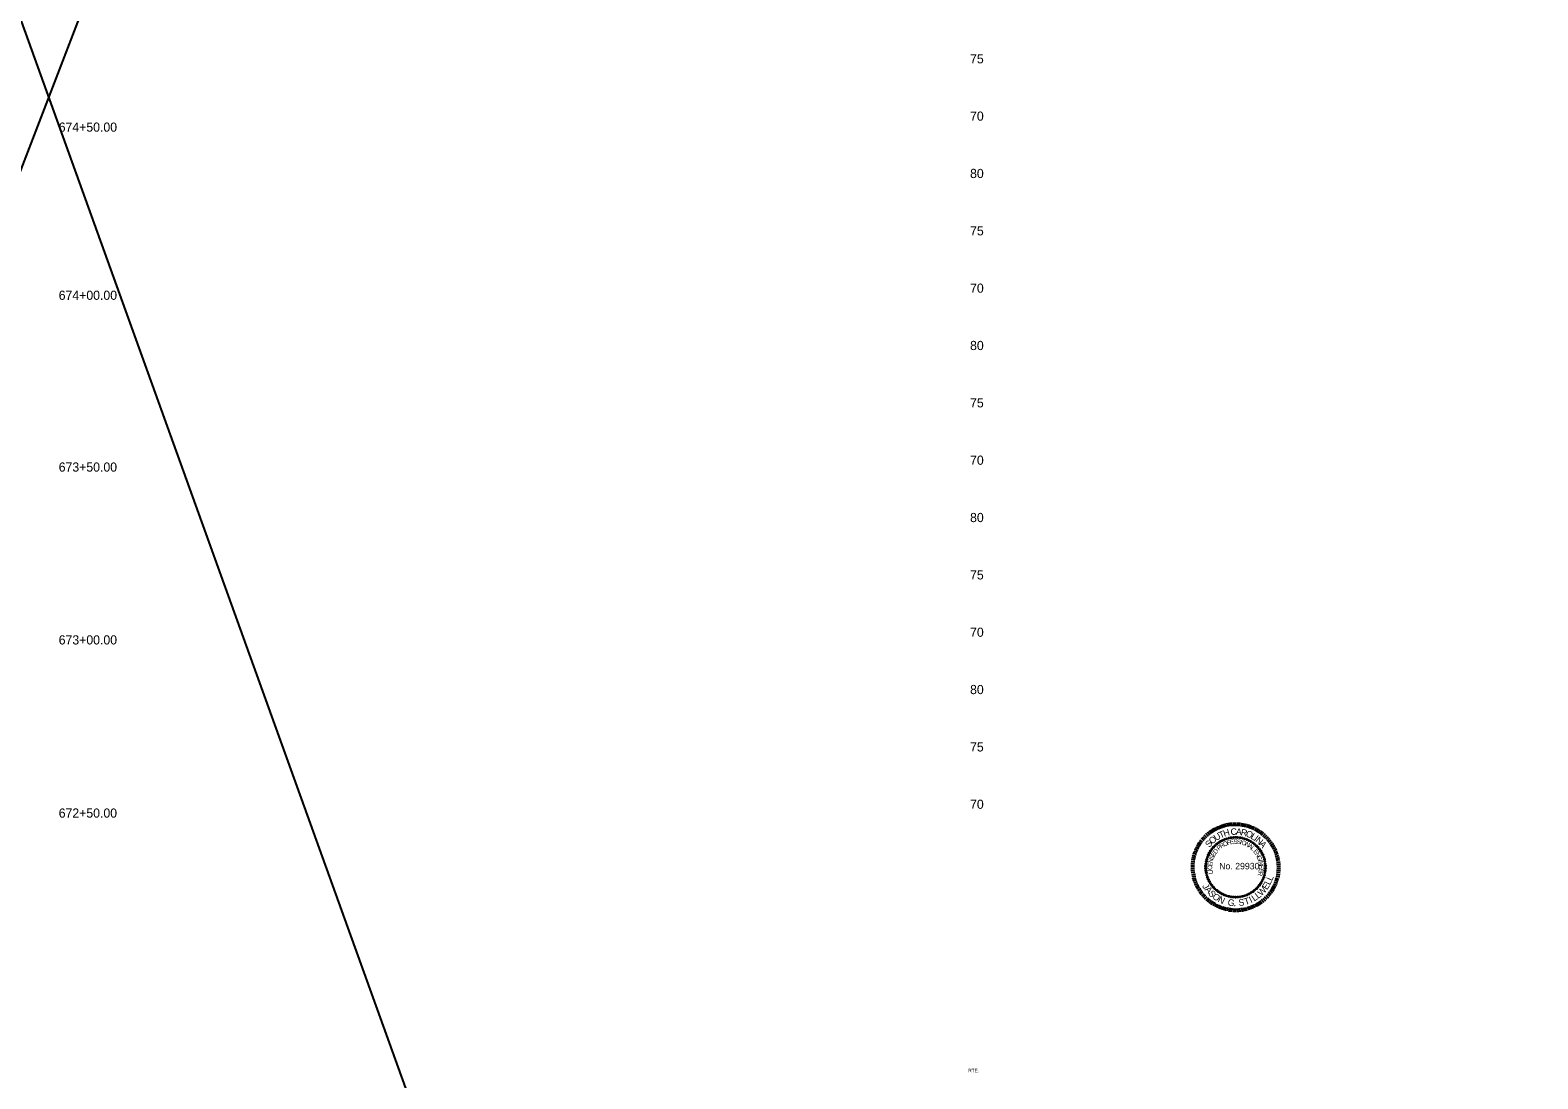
# Model space of a CAD drawing. Extents: x 952 to 1206, y 942 to 2399.
# Drawn here: x 1074.9 to 1206.4, y 1216.5 to 1307.9 of the extents above; entities that cross this region are included whole.
import ezdxf

# ---------------------------------------------------------------- set-up
doc = ezdxf.new("R2010")
doc.units = 0
for name, color, linetype in [('Default', 7, 'Continuous'), ('RD_SHT_TX', 7, 'Continuous'), ('RD_TX_PEShield', 7, 'Continuous'), ('RD_XS_TX_Elev_EX', 7, 'Continuous'), ('RD_XS_TX_Station', 7, 'Continuous')]:
    doc.layers.add(name, color=color, linetype=linetype)

# ---------------------------------------------------------------- blocks, each defined once
blk = doc.blocks.new('STILLWELL')
at = {"layer": 'RD_TX_PEShield'}
for p, q in [((-25.1, 24.7), (-27.4, 27.1)), ((-23.8, 25.9), (-26, 28.4)), ((-22.5, 27), (-24.5, 29.6)), ((-21.1, 28.1), (-23, 30.7)), ((-19.7, 29.1), (-21.5, 31.8)), ((-18.2, 30), (-19.9, 32.8)), ((-16.7, 30.8), (-18.2, 33.7)), ((-15.1, 31.6), (-16.5, 34.6)), ((-13.6, 32.3), (-14.8, 35.3)), ((-11.9, 32.9), (-13, 36)), ((-10.3, 33.4), (-11.2, 36.6)), ((-8.6, 33.9), (-9.4, 37.1)), ((-6.9, 34.3), (-7.5, 37.5)), ((-5.2, 34.6), (-5.7, 37.8)), ((-3.5, 34.8), (-3.8, 38)), ((-1.8, 34.9), (-1.9, 38.2)), ((0, 34.9), (0, 38.2)), ((1.7, 34.9), (1.9, 38.2)), ((3.4, 34.8), (3.7, 38)), ((5.2, 34.6), (5.6, 37.8)), ((6.9, 34.3), (7.5, 37.5)), ((8.6, 33.9), (9.3, 37.1)), ((10.2, 33.4), (11.2, 36.6)), ((11.9, 32.9), (13, 36)), ((13.5, 32.3), (14.7, 35.3)), ((15.1, 31.6), (16.5, 34.6)), ((16.6, 30.8), (18.2, 33.7)), ((18.2, 30), (19.8, 32.8)), ((19.6, 29.1), (21.4, 31.8)), ((21.1, 28.1), (23, 30.7)), ((22.4, 27), (24.5, 29.6)), ((23.8, 25.9), (25.9, 28.4)), ((25, 24.7), (27.3, 27.1)), ((-32.9, 13.4), (-35.9, 14.7)), ((-32.2, 15), (-35.1, 16.4)), ((-31.4, 16.5), (-34.2, 18.1)), ((-30.5, 18), (-33.3, 19.7)), ((-29.5, 19.4), (-32.2, 21.3)), ((-28.5, 20.9), (-31.1, 22.8)), ((-27.4, 22.2), (-29.9, 24.3)), ((-26.3, 23.5), (-28.7, 25.7)), ((26.2, 23.5), (28.6, 25.7)), ((27.4, 22.2), (29.9, 24.3)), ((28.5, 20.9), (31.1, 22.8)), ((29.5, 19.4), (32.2, 21.3)), ((30.4, 18), (33.2, 19.7)), ((31.3, 16.5), (34.2, 18.1)), ((32.1, 15), (35.1, 16.4)), ((32.9, 13.4), (35.9, 14.7)), ((-35.9, -0.1), (-39.2, 0)), ((-35.8, 1.7), (-39.1, 1.9)), ((-35.6, 3.4), (-38.9, 3.8)), ((-35.4, 5.1), (-38.6, 5.7)), ((-35.1, 6.8), (-38.2, 7.5)), ((-34.6, 8.5), (-37.8, 9.4)), ((-34.1, 10.2), (-37.2, 11.2)), ((-33.6, 11.8), (-36.6, 12.9)), ((33.5, 11.8), (36.6, 12.9)), ((34.1, 10.2), (37.2, 11.2)), ((34.6, 8.5), (37.7, 9.4)), ((35, 6.8), (38.2, 7.5)), ((35.3, 5.1), (38.5, 5.7)), ((35.6, 3.4), (38.8, 3.8)), ((35.7, 1.7), (39, 1.9)), ((35.8, -0.1), (39.1, 0)), ((-35.9, -1.8), (-39.2, -1.9)), ((-35.8, -3.5), (-39.1, -3.8)), ((-35.6, -5.3), (-38.9, -5.6)), ((-35.4, -7), (-38.6, -7.5)), ((-35.1, -8.7), (-38.2, -9.4)), ((-34.6, -10.4), (-37.8, -11.2)), ((-34.1, -12), (-37.2, -13)), ((34.1, -12), (37.2, -13)), ((34.6, -10.4), (37.7, -11.2)), ((35, -8.7), (38.2, -9.4)), ((35.3, -7), (38.5, -7.5)), ((35.6, -5.3), (38.8, -5.6)), ((35.7, -3.5), (39, -3.8)), ((35.8, -1.8), (39.1, -1.9)), ((-33.6, -13.6), (-36.6, -14.8)), ((-32.9, -15.3), (-35.9, -16.6)), ((-32.2, -16.8), (-35.1, -18.3)), ((-31.4, -18.4), (-34.2, -19.9)), ((-30.5, -19.9), (-33.3, -21.6)), ((-29.5, -21.3), (-32.2, -23.2)), ((-28.5, -22.7), (-31.1, -24.7)), ((-27.4, -24.1), (-29.9, -26.2)), ((-26.3, -25.4), (-28.7, -27.6)), ((26.2, -25.4), (28.6, -27.6)), ((27.4, -24.1), (29.9, -26.2)), ((28.5, -22.7), (31.1, -24.7)), ((29.5, -21.3), (32.2, -23.2)), ((30.4, -19.9), (33.2, -21.6)), ((31.3, -18.4), (34.2, -19.9)), ((32.1, -16.8), (35.1, -18.3)), ((32.9, -15.3), (35.9, -16.6)), ((33.5, -13.6), (36.6, -14.8)), ((-25.1, -26.6), (-27.4, -28.9)), ((-23.8, -27.8), (-26, -30.2)), ((-22.5, -28.9), (-24.5, -31.4)), ((-21.1, -29.9), (-23, -32.6)), ((-19.7, -30.9), (-21.5, -33.7)), ((-18.2, -31.8), (-19.9, -34.7)), ((-16.7, -32.7), (-18.2, -35.6)), ((-15.1, -33.5), (-16.5, -36.4)), ((-13.6, -34.1), (-14.8, -37.2)), ((-11.9, -34.8), (-13, -37.8)), ((-10.3, -35.3), (-11.2, -38.4)), ((-8.6, -35.8), (-9.4, -38.9)), ((-6.9, -36.1), (-7.5, -39.3)), ((-5.2, -36.4), (-5.7, -39.7)), ((-3.5, -36.6), (-3.8, -39.9)), ((-1.8, -36.8), (-1.9, -40)), ((0, -36.8), (0, -40.1)), ((1.7, -36.8), (1.9, -40)), ((3.4, -36.6), (3.7, -39.9)), ((5.2, -36.4), (5.6, -39.7)), ((6.9, -36.1), (7.5, -39.3)), ((8.6, -35.8), (9.3, -38.9)), ((10.2, -35.3), (11.2, -38.4)), ((11.9, -34.8), (13, -37.8)), ((13.5, -34.1), (14.7, -37.2)), ((15.1, -33.5), (16.5, -36.4)), ((16.6, -32.7), (18.2, -35.6)), ((18.2, -31.8), (19.8, -34.7)), ((19.6, -30.9), (21.4, -33.7)), ((21.1, -29.9), (23, -32.6)), ((22.4, -28.9), (24.5, -31.4)), ((23.8, -27.8), (25.9, -30.2)), ((25, -26.6), (27.3, -28.9))]:
    blk.add_line(p, q, dxfattribs=at)
for centre in [(-21.9, 13.2), (-20.7, 14.9), (-19.5, 16.4), (-18.1, 17.8), (-16.6, 19.2), (-15, 20.4), (-13.3, 21.5), (-11.6, 22.4), (-9.8, 23.2), (-7.9, 23.9), (-6, 24.4), (-4, 24.8), (-2, 25), (0, 25.1), (2, 25), (3.9, 24.8), (5.9, 24.4), (7.8, 23.9), (9.7, 23.2), (11.5, 22.4), (13.3, 21.5), (15, 20.4), (16.5, 19.2), (18, 17.8), (19.4, 16.4), (20.7, 14.9), (21.8, 13.2), (-26.1, 0.1), (-25.9, 2.1), (-25.6, 4), (-25.1, 6), (-24.5, 7.9), (-23.8, 9.7), (-22.9, 11.5), (22.9, 11.5), (23.7, 9.7), (24.5, 7.9), (25.1, 6), (25.5, 4), (25.8, 2.1), (26, 0.1), (-26.1, -1.9), (-25.9, -3.9), (-25.6, -5.9), (-25.1, -7.8), (-24.5, -9.7), (-23.8, -11.6), (-22.9, -13.4), (22.9, -13.4), (23.7, -11.6), (24.5, -9.7), (25.1, -7.8), (25.5, -5.9), (25.8, -3.9), (26, -1.9), (-21.9, -15.1), (-20.7, -16.7), (-19.5, -18.3), (-18.1, -19.7), (-16.6, -21), (-15, -22.2), (-13.3, -23.3), (-11.6, -24.3), (-9.8, -25.1), (-7.9, -25.8), (-6, -26.3), (-4, -26.7), (3.9, -26.7), (5.9, -26.3), (7.8, -25.8), (9.7, -25.1), (11.5, -24.3), (13.3, -23.3), (15, -22.2), (16.5, -21), (18, -19.7), (19.4, -18.3), (20.7, -16.7), (21.8, -15.1), (-2, -26.9), (0, -27), (2, -26.9)]:
    blk.add_circle(centre, 0.49, dxfattribs=at)
for s, height, rotation, p in [('U', 5.68, 32.2152, (-16.9, 21.8)), ('T', 5.68, 23.5044, (-13.2, 24.1)), ('H', 5.68, 16.1357, (-9.9, 25.6)), ('C', 5.68, 4.076, (-4.2, 27.1)), ('A', 5.68, 355.3651, (0.1, 27.4)), ('R', 5.68, 347.3188, (4.1, 27.1)), ('O', 5.68, 338.6079, (8.3, 26.2)), ('L', 5.68, 329.226, (12.6, 24.4)), ('I', 5.68, 322.5218, (15.5, 22.8)), ('S', 5.68, 49.6435, (-22.9, 15.8)), ('O', 5.68, 41.5972, (-20.4, 18.8)), ('D', 3.92, 52.5376, (-17.1, 10.3)), ('P', 3.92, 41.0022, (-14.5, 13.5)), ('R', 3.92, 33.3057, (-12.5, 15.3)), ('O', 3.92, 24.9735, (-10, 16.9)), ('F', 3.92, 15.9995, (-7.1, 18.3)), ('E', 3.92, 8.9511, (-4.7, 19)), ('S', 3.92, 1.2546, (-1.9, 19.4)), ('S', 3.92, 353.558, (0.8, 19.5)), ('I', 3.92, 345.8615, (3.5, 19.2)), ('O', 3.92, 342.6583, (4.7, 19)), ('N', 3.92, 333.6842, (7.7, 18)), ('A', 3.92, 325.3521, (10.4, 16.7)), ('L', 3.92, 317.6555, (12.6, 15.1)), ('E', 3.92, 308.0396, (15.1, 12.8)), ('N', 5.68, 319.1729, (16.8, 21.8)), ('A', 5.68, 310.4621, (20.1, 19)), ('C', 3.92, 92.2915, (-20.4, -3.2)), ('E', 3.92, 83.9594, (-20.5, -0.2)), ('N', 3.92, 76.2628, (-20.2, 2.5)), ('S', 3.92, 67.9307, (-19.5, 5.4)), ('E', 3.92, 60.2341, (-18.5, 7.9)), ('N', 3.92, 300.343, (16.8, 10.6)), ('G', 3.92, 292.0109, (18.3, 8.1)), ('I', 3.92, 283.0368, (19.5, 5.1)), ('N', 3.92, 279.8336, (19.8, 4)), ('E', 3.92, 271.5014, (20.3, 1.1)), ('I', 3.92, 95.4947, (-20.2, -4.3)), ('L', 3.92, 101.9075, (-19.7, -6.6)), ('R', 3.92, 256.1083, (20.1, -4.4)), ('E', 3.92, 263.8049, (20.4, -1.7)), ('L', 5.68, 65.098, (30, -16.9)), ('L', 5.68, 65.098, (31.6, -13.3)), ('J', 5.68, 299.033, (-29.4, -17.3)), ('A', 5.68, 310.5887, (-27.2, -20.6)), ('S', 5.68, 310.5887, (-24.3, -24)), ('O', 5.68, 321.0072, (-20.8, -27.4)), ('N', 5.68, 333.4326, (-16, -30.8)), ('L', 5.68, 34.0644, (16.2, -30.9)), ('L', 5.68, 37.6708, (19.6, -28.7)), ('W', 5.68, 47.0518, (22.6, -26.4)), ('E', 5.68, 56.4327, (27.3, -21.1)), ('G', 5.68, 352.2045, (-7.2, -34.2)), ('.', 5.68, 0.8698, (-1.8, -34.9)), ('S', 5.68, 8.0826, (2.9, -34.8)), ('T', 5.68, 18.9019, (8.5, -33.9)), ('I', 5.68, 25.3991, (13.3, -32.2))]:
    blk.add_text(s, height=height, rotation=rotation, dxfattribs=at).set_placement(p)
blk.add_text('No. 29930', height=5.68, dxfattribs=at).set_placement((-14.3, -2.8))

msp = doc.modelspace()

# ---------------------------------------------------------------- linework, layer by layer
at = {"layer": 'RD_SHT_TX'}
for p, q in [((951.99, 979.01), (1182.92, 1577.73)), ((980.77, 1567.94), (1206.44, 941.58))]:
    msp.add_line(p, q, dxfattribs=at)

# ---------------------------------------------------------------- block references
at = {"layer": 'Default', "xscale": 0.1, "yscale": 0.10000000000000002}
msp.add_blockref('STILLWELL', (1180.08, 1235), dxfattribs=at)

# ---------------------------------------------------------------- texts
at = {"layer": 'RD_SHT_TX'}
msp.add_text('RTE.', height=0.3, dxfattribs=at).set_placement((1156.76, 1217.03))
at = {"layer": 'RD_XS_TX_Elev_EX'}
for s, p in [('75', (1156.92, 1305)), ('70', (1156.92, 1300)), ('80', (1156.92, 1295)), ('75', (1156.92, 1290)), ('70', (1156.92, 1285)), ('80', (1156.92, 1280)), ('75', (1156.92, 1275)), ('70', (1156.92, 1270)), ('80', (1156.92, 1265)), ('75', (1156.92, 1260)), ('70', (1156.92, 1255)), ('80', (1156.92, 1250)), ('75', (1156.92, 1245)), ('70', (1156.92, 1240))]:
    msp.add_text(s, height=0.8, dxfattribs=at).set_placement(p)
at = {"layer": 'RD_XS_TX_Station'}
for s, p in [('674+50.00', (1077.44, 1299.04)), ('674+00.00', (1077.44, 1284.38)), ('673+50.00', (1077.44, 1269.4)), ('673+00.00', (1077.44, 1254.33)), ('672+50.00', (1077.44, 1239.23))]:
    msp.add_text(s, height=0.8, dxfattribs=at).set_placement(p)

doc.saveas('drawing.dxf')
